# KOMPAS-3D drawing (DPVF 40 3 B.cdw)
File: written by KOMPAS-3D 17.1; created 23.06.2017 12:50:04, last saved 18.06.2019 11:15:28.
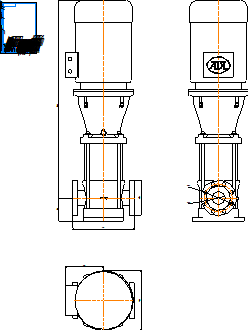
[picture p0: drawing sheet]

Sheet 1: A4, portrait

Title block, sheet 1: name: DPVF 40 3 B; material: Внимание! Данный продукт является объектом авторского права ООО «Торговый Дом АДЛ». / Запрещается изменение, копирование, распространение / (в том числе путем копирования на другие сайты и ресурсы в Интернете) / или любое иное использование информации и объектов без предварительного / согласия правообладателя (ООО «Торговый Дом АДЛ»).; scale: 1:1; sheets: 1; organisation: ООО "Торговый дом АДЛ"; sheet format: A4; stored path: C:\Клочков АВ\Насосы\DP PAMS\DPVF 40\Компас 2d\DPVF 40 3 B.cdw

Views: Спереди 1
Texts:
  Клочков АВ
  ООО АДЛ ГРУПП
Dimensions and other numbers on the sheet: 365; 223; 350; 209,6; 1156,5; 140; 168,1; 76,2; 1:1; 1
